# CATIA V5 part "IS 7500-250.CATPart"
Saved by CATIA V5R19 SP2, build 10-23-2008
Part number: IS 7500-250
Bounding box of the stored display mesh (mm): x -74.81 to 74.81, y -74.81 to 74.81, z 0 to 655
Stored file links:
  C:\Users\Bora\Desktop\3D Katı model\IS serisi\IS 7500\IS 7500-250.CATPart
  C:\Program Files\Dassault Systemes\B19\intel_a\reffiles\standard\MetricThickPitch.txt
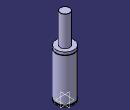
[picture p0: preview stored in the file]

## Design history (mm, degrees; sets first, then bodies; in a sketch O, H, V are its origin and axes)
Body1 (main body)
  Sketch1 on yz-plane, origin (0, 0, 0), H (0, 1, 0), V (0, 0, 1)
    point P1 (75, 380)
    point P4 (75, 375)
    point P7 (40, 654)
    point P9 (40, 654)
    point P13 (75, 380)
    point P14 (75, 375)
    line L1 (75, 380) -> (75, 402)
    line L2 (75, 15) -> (75, 375)
    line L3 (71, 15) -> (71, 8)
    arc A1 centre (39, 654) radius 1 from (40, 654) to (39, 655) ccw
    line L4 (40, 654) -> (40, 402)
    line L5 (75, 0) -> (75, 8)
    arc A2 centre (75, 377.5) radius 2.5 from (75, 380) to (75, 375) ccw
    line L6 (39, 655) -> (0, 655)
    point P15 (0, 655)
    line L7 (40, 402) -> (75, 402)
    line L8 (0, 0) -> (75, 0)
    line L9 (71, 15) -> (75, 15)
    line L10 (71, 8) -> (75, 8)
    coincidence: P15 V, P1 P13, P4 P14, P7 P9
    tangency: L6 A1
    horizontal: L7 H, L8 H, L9 H, L10 H
  Shaft1: profile Sketch1, axis Sketch1.V, angle 360
  Sketch2 on face of Shaft1 from Sketch1.L8, origin (0, 0, 0), H (1, 0, 0), V (0, -1, 0)
    point P1 (50, 0)
    distance P1 V = 50
  Hole1: placed by Sketch2, at (50, 0, 0) direction (0, 0, 1), diameter 8.376, depth 16, threaded "M10", thread diameter 10, thread depth 16, pitch 1.5
  CircPattern1: of Hole1, instances 4, angular step 90, axis from xy-plane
